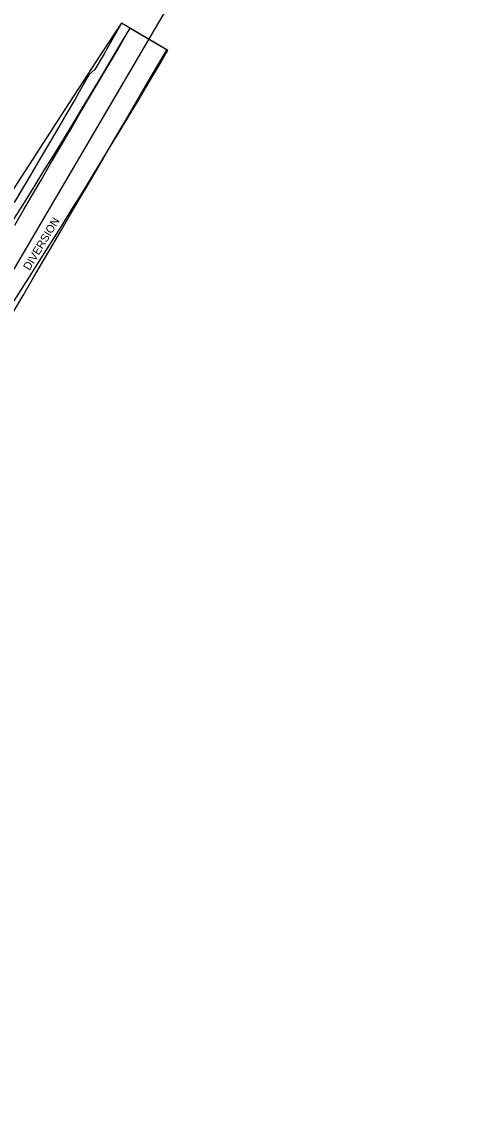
# Model space of a CAD drawing. Extents: x 1160458 to 1162290, y 615427 to 618737.
# Drawn here: x 1162037 to 1162287, y 617839 to 618437 of the extents above; entities that cross this region are included whole.
import ezdxf

# ---------------------------------------------------------------- set-up
doc = ezdxf.new("R2010")
doc.units = 0
for name, color, linetype in [('1', 7, 'Continuous'), ('D_Roadway_Edge_Pavement', 7, 'Continuous'), ('D_Roadway_Edge_TW', 7, 'Continuous'), ('D_Slope_Fill', 7, 'Continuous'), ('D_Text_Standard', 7, 'Continuous'), ('FW milling for gen plans', 7, 'Continuous'), ('Old pavement area_not used', 7, 'Continuous'), ('Shoulder work for div plan (NB)', 7, 'Continuous')]:
    doc.layers.add(name, color=color, linetype=linetype)

msp = doc.modelspace()

# ---------------------------------------------------------------- linework, layer by layer
at = {"layer": '1'}
msp.add_line((1161209.81, 616899.51), (1162286.6, 618733.81), dxfattribs=at)
at = {"layer": 'D_Roadway_Edge_Pavement'}
msp.add_line((1162096.59, 618433.62), (1162117.19, 618421.51), dxfattribs=at)
at = {"layer": 'D_Roadway_Edge_TW'}
for radius in [4188, 4212]:
    msp.add_arc((1158484.81, 620553.82), radius, 320.71863, 329.58575, dxfattribs=at)
at = {"layer": 'D_Slope_Fill'}
msp.add_lwpolyline([(1161864.33, 618096.78), (1161892.38, 618137.82), (1161920.38, 618178.92), (1161947.2, 618220.79), (1161974.76, 618262.22), (1162003.5, 618302.78), (1162031.65, 618343.82), (1162058.74, 618385.58), (1162080.66, 618419.35), (1162091.79, 618436.2), (1162091.79, 618436.2)], dxfattribs=at)
at = {"layer": 'FW milling for gen plans'}
msp.add_line((1162117.19, 618421.51), (1162116.63, 618421.83), dxfattribs=at)
at = {"layer": 'Old pavement area_not used'}
msp.add_line((1162116.63, 618421.83), (1162091.89, 618436.38), dxfattribs=at)
for points in [[(1162091.89, 618436.38), (1162087.28, 618428.32), (1162082.31, 618419.64), (1162077.34, 618410.96), (1162073.95, 618408)], [(1162096.14, 618386.74), (1162100.16, 618393.66), (1162107.73, 618406.6), (1162112.78, 618415.24), (1162116.63, 618421.83)], [(1162073.95, 618408), (1162069.4, 618400.04), (1162066.43, 618394.87), (1162061.43, 618386.21), (1162060.67, 618384.91), (1162055.63, 618376.26), (1162052.51, 618370.92), (1162047.43, 618362.29), (1162042.35, 618353.68), (1162038.3, 618346.83), (1162033.2, 618338.23)], [(1162033, 618278.87), (1162038.05, 618287.5), (1162043.1, 618296.13), (1162048.15, 618304.76), (1162053.21, 618313.39), (1162058.26, 618322.02), (1162063.31, 618330.65), (1162065.84, 618334.96), (1162070.89, 618343.59), (1162075.94, 618352.22), (1162080.99, 618360.85), (1162083.51, 618365.17), (1162088.57, 618373.8), (1162093.62, 618382.43), (1162096.14, 618386.74)]]:
    msp.add_lwpolyline(points, dxfattribs=at)
at = {"layer": 'Shoulder work for div plan (NB)'}
for p, q in [((1162091.89, 618436.38), (1162087.28, 618428.32)), ((1162096.59, 618433.62), (1162091.89, 618436.38)), ((1162094.61, 618430.25), (1162096.59, 618433.62)), ((1162087.28, 618428.32), (1162082.31, 618419.64)), ((1162082.31, 618419.64), (1162077.34, 618410.96)), ((1162079.4, 618404.51), (1162084.35, 618412.78)), ((1162077.34, 618410.96), (1162073.95, 618408))]:
    msp.add_line(p, q, dxfattribs=at)
for points in [[(1162084.35, 618412.78), (1162084.48, 618413.01), (1162089.55, 618421.63), (1162094.61, 618430.25)], [(1162073.95, 618408), (1162071.68, 618404.02), (1162069.4, 618400.04), (1162066.43, 618394.87), (1162061.43, 618386.21), (1162060.67, 618384.91), (1162058.15, 618380.58), (1162055.63, 618376.26), (1162052.51, 618370.92), (1162047.43, 618362.29), (1162042.35, 618353.68), (1162038.3, 618346.83), (1162035.75, 618342.53)], [(1162033.49, 618325.83), (1162038.52, 618334.47), (1162042.87, 618341.93), (1162047.9, 618350.57), (1162052.93, 618359.21), (1162057.97, 618367.85), (1162063.01, 618376.49), (1162064.25, 618378.62), (1162069.3, 618387.25), (1162074.35, 618395.88), (1162079.4, 618404.51)]]:
    msp.add_lwpolyline(points, dxfattribs=at)

# ---------------------------------------------------------------- texts
at = {"layer": 'D_Text_Standard'}
msp.add_text('DIVERSION', height=4.375, rotation=58.81561, dxfattribs=at).set_placement((1162041.56, 618300.87))

doc.saveas('drawing.dxf')
